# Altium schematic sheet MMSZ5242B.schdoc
size 127 x 101 mm
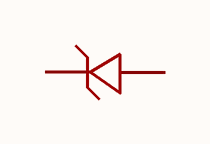
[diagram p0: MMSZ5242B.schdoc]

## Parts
ZD?  mmsz5242b_c21567  [SOD-123_L2.8-W1.8-LS3.7-RD]  (value not drawn)

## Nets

Not connected (* = marked no-connect by the designer): ZD? 1(K) 2(A)

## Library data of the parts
ZD? = mmsz5242b_c21567: 二极管配置:1个独立式;稳压值(标称值):12V;稳压值(范围):11.4V~12.6V;耗散功率(Pd):350mW;; Manufacturer: CJ(江苏长电/长晶); AddInBom: yes; ModelId: 7884390a25fb4c08947731ebfba7e3f8; ModelTransform: 144.8816,62.992,0,0,0,0,0,0,0; Diode Configuration: 1个独立式; Zener Voltage(Nom): 12V; Reverse Leakage Current (Ir): 1uA; Pd - Power Dissipation: 350mW; Impedance(Zzt): 30Ω; Impedance(Zzk): 600Ω; Operating Junction Temperature Range: -65℃~+150℃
